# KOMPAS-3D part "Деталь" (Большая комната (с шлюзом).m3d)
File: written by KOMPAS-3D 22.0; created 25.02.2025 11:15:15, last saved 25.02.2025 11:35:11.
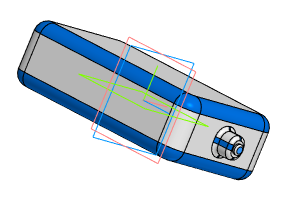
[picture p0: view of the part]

Document properties: Автор: Пользователь Windows; Полное имя файла: C:\Users\Student\Documents\Картошечка\База Сабнатика\Большая комната\Большая комната (с шлюзом).m3d

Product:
- Body: Тело 1
    Масса: 2.227738
- Part/product: Деталь
    Масса: 2.237738

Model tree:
1. Эскиз:1
2. Элемент выдавливания:1
     Расстояние 1 = 35
3. Скругление:2  (with: Элемент выдавливания:1)
     Радиус = 10
4. Скругление:1  (with: Элемент выдавливания:1)
     Радиус = 7
5. Эскиз:2  (with: Элемент выдавливания:1)
6. Элемент выдавливания:2
     Расстояние 1 = 10
7. Скругление:3  (with: Элемент выдавливания:2)
     Радиус = 2
8. Эскиз:3  (with: Элемент выдавливания:2)
9. Элемент выдавливания:3
     Расстояние 1 = 2
10. Скругление:4  (with: Элемент выдавливания:3)
     Радиус = 1
11. Скругление:5  (with: Элемент выдавливания:2)
     Радиус = 2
